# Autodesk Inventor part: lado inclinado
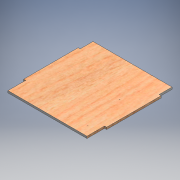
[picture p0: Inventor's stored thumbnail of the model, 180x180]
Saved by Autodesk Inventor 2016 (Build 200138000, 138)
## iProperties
Created: 2016-06
Part Number: lado inclinado
Material: Genérico
Document SubType Name: Modeling
Designer: adm
Density: 1 g/cm^3
Appearance: Valor por defecto
Author: adm
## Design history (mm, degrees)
sketch "Boceto1"
  geometry: L1 (-57, 59)-(59, 59); L2 (62, 40)-(62, -40); L3 (59, -71)-(-57, -71); L4 (-60, -40)-(-60, 40); L5 (-76.795, 75.588)-(57.893, -56.983); L6 (60, 73)-(-57, -69.35); L7 (-57, 59)-(-57, 40); L8 (-57, -40)-(-57, -71); L9 (59, 59)-(59, 40); L10 (59, -40)-(59, -71); L11 (59, -40)-(62, -40); L12 (-60, -40)-(-57, -40); L13 (-60, 40)-(-57, 40); L14 (59, 40)-(62, 40); 1 further point
  constraints: 28 end point, 3 point on line, 2 parallel, 1 horizontal, 1 perpendicular
  dimensions: "d1" = 130 distance of L6.start L5.end; "d9" = 3 distance between parallel lines of L7 L4; "d10" = 3 distance between parallel lines of L8 L4; "d11" = 3 distance between parallel lines of L10 L2; "d12" = 3 distance between parallel lines of L2 L9; "d13" = 122 distance between parallel lines of L2 L4; "d17" = 130 distance between parallel lines of L3 L1; "d18" = 31 distance between parallel lines of L3 L12
extrude "Extrusión1" new body sketch "Boceto1" distance "d7" = 3; taper "d8" = 0 deg
sketch "Boceto2"
  geometry: L1 (-57, -40)-(-57, -71) reference; L2 (59, -71)-(59, -40) reference; L3 (-57, -71)-(59, -71); L4 (59, -71)-(59, -66); L5 (59, -66)-(-57, -66); L6 (-57, -66)-(-57, -71); 1 further point
  constraints: 8 end point, 2 parallel, 1 horizontal, 1 perpendicular, 1 point on line
  dimensions: "d14" = 5 distance of L4.end L3.end
extrude "Extrusión2" cut sketch "Boceto2" distance "d15" = 10; taper "d16" = 0 deg
node "Sólido1"
other parameters: "d3" = 33, "d4" = 33, "d5" = 3, "d6" = 3
